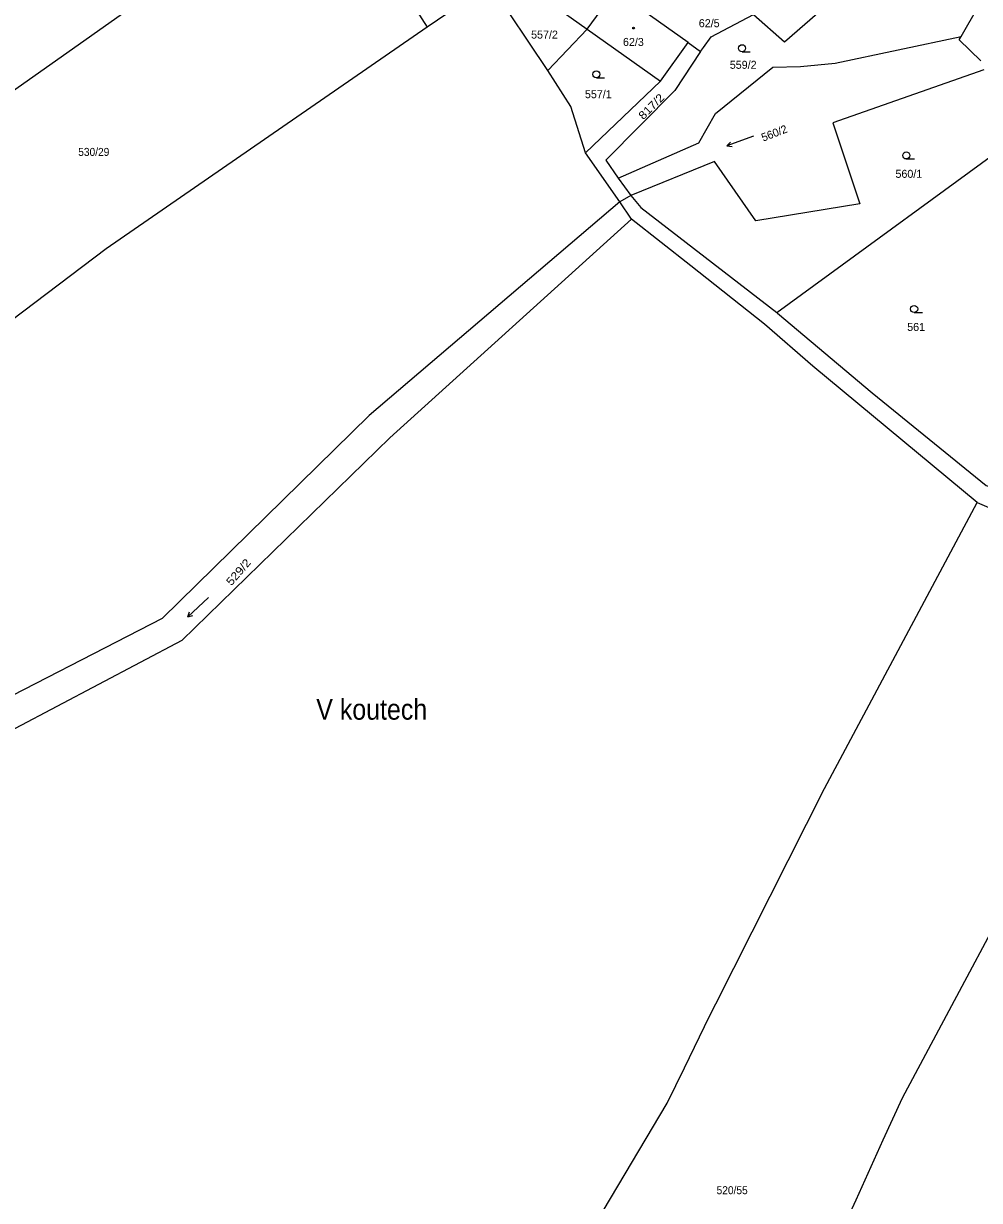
# Model space of a CAD drawing. Extents: x -687135 to -684370, y -1007309 to -1005782.
# Drawn here: x -685399.4 to -685196.4, y -1006924.3 to -1006674.4 of the extents above; entities that cross this region are included whole.
import ezdxf
from ezdxf.enums import TextEntityAlignment as Align

# ---------------------------------------------------------------- set-up
doc = ezdxf.new("R2010")
doc.units = 0
doc.header["$LTSCALE"] = 0.68
for name, color, linetype, lineweight in [('1', 7, 'Continuous', 25), ('3', 7, 'Continuous', 25), ('5', 7, 'Continuous', 25), ('7', 7, 'Continuous', 13)]:
    doc.layers.add(name, color=color, linetype=linetype, lineweight=lineweight)
doc.layers.add('2', color=7, linetype='Continuous')

msp = doc.modelspace()

# ---------------------------------------------------------------- linework, layer by layer
at = {"layer": '1'}
for p, q in [((-685335.02, -1006641.79), (-685313.7, -1006675.14)), ((-685279.72, -1006675.62), (-685273.74, -1006667.38)), ((-685279.72, -1006675.62), (-685288.04, -1006684.34)), ((-685258.28, -1006678.42), (-685255.62, -1006680.32)), ((-685280.06, -1006701.85), (-685264.15, -1006686.64)), ((-685272.78, -1006712.27), (-685280.06, -1006701.85)), ((-685273.1, -1006707.25), (-685270.46, -1006710.92)), ((-685270.46, -1006710.92), (-685272.78, -1006712.27)), ((-685270.27, -1006715.95), (-685272.78, -1006712.27)), ((-685196.87, -1006776.1), (-685155.44, -1006794.14))]:
    msp.add_line(p, q, dxfattribs=at)
for points in [[(-685413.15, -1006696.73), (-685384.89, -1006676.88), (-685341.29, -1006645.97), (-685335.02, -1006641.79)], [(-685273.1, -1006707.25), (-685256.03, -1006699.69), (-685252.45, -1006693.52), (-685240.26, -1006683.63), (-685234.38, -1006683.48), (-685227.07, -1006682.77), (-685200.27, -1006677.13), (-685196.71, -1006670.85), (-685212.49, -1006656.18)], [(-685244.38, -1006672.48), (-685237.81, -1006678.26), (-685212.49, -1006656.18)], [(-685296.58, -1006663.55), (-685287.7, -1006669.89), (-685279.72, -1006675.62)], [(-685280.06, -1006701.85), (-685283.18, -1006692.03), (-685288.04, -1006684.34), (-685300.34, -1006666.05), (-685313.7, -1006675.14)], [(-685279.72, -1006675.62), (-685264.15, -1006686.64), (-685258.28, -1006678.42), (-685273.74, -1006667.38)], [(-685255.62, -1006680.32), (-685255.04, -1006679.45), (-685253.41, -1006677.18), (-685244.38, -1006672.48)], [(-685313.7, -1006675.14), (-685381.87, -1006722.26), (-685417.2, -1006748.9), (-685442.1, -1006766.87), (-685471.35, -1006787.14), (-685521.55, -1006819.13)], [(-685196.12, -1006682.34), (-685200.74, -1006677.86), (-685200.27, -1006677.13)], [(-685255.62, -1006680.32), (-685261.11, -1006688.62), (-685275.78, -1006703.42), (-685273.1, -1006707.25)], [(-685195.49, -1006684.24), (-685227.55, -1006695.45), (-685221.81, -1006712.7), (-685243.9, -1006716.28), (-685252.71, -1006703.66), (-685270.46, -1006710.92)], [(-685270.46, -1006710.92), (-685268.32, -1006713.45), (-685239.42, -1006735.75), (-685184.75, -1006695.82)], [(-685272.78, -1006712.27), (-685326.02, -1006757.61), (-685369.95, -1006800.7), (-685411.54, -1006822.08), (-685479.62, -1006851.9)], [(-685270.27, -1006715.95), (-685321.6, -1006762.38), (-685365.8, -1006805.42), (-685410.08, -1006828.78), (-685472.04, -1006855.16)], [(-685196.87, -1006776.1), (-685231.83, -1006747.11), (-685242.03, -1006738.2), (-685257.69, -1006725.86), (-685270.27, -1006715.95)], [(-685239.42, -1006735.75), (-685239.28, -1006735.88), (-685219.19, -1006752.8), (-685194.99, -1006772.45), (-685194.34, -1006772.72)], [(-685344.34, -1007065.04), (-685332.49, -1007031.1), (-685312.53, -1006989.57), (-685304.62, -1006974.15), (-685262.73, -1006903.67), (-685259.07, -1006896.13), (-685253.74, -1006885.14), (-685252.41, -1006882.51), (-685229.3, -1006836.82), (-685196.87, -1006776.1)], [(-685301.77, -1007070.79), (-685288.08, -1007040.77), (-685248.53, -1006968.29), (-685233.07, -1006943.13), (-685224.8, -1006928.93), (-685222.62, -1006924.15), (-685216.83, -1006911.45), (-685212.76, -1006902.52), (-685180.81, -1006842.75), (-685155.44, -1006794.14)]]:
    msp.add_lwpolyline(points, dxfattribs=at)
at = {"layer": '3'}
for p, q in [((-685246.823, -1006680.38), (-685245.073, -1006680.38)), ((-685277.763, -1006685.92), (-685276.013, -1006685.92)), ((-685250.048, -1006700.374), (-685249.301, -1006699.568)), ((-685211.953, -1006703.15), (-685210.203, -1006703.15)), ((-685210.283, -1006735.75), (-685208.533, -1006735.75)), ((-685364.512, -1006800.361), (-685364.14, -1006799.328))]:
    msp.add_line(p, q, dxfattribs=at)
for points in [[(-685244.41, -1006698.322), (-685250.048, -1006700.374), (-685248.958, -1006700.511)], [(-685360.124, -1006796.269), (-685364.512, -1006800.361), (-685363.456, -1006800.062)]]:
    msp.add_lwpolyline(points, dxfattribs=at)
for centre in [(-685246.8229, -1006679.6298), (-685277.7629, -1006685.1698), (-685211.9529, -1006702.3998), (-685210.2829, -1006734.9998)]:
    msp.add_circle(centre, 0.75, dxfattribs=at)
at = {"layer": '5'}
msp.add_circle((-685269.8668, -1006675.3592), 0.175, dxfattribs=at)

# ---------------------------------------------------------------- texts
at = {"layer": '2'}
for s, p in [('62/5', (-685256.01, -1006675.169)), ('557/2', (-685291.62, -1006677.59)), ('62/3', (-685272.11, -1006679.15)), ('559/2', (-685249.43, -1006684)), ('557/1', (-685280.19, -1006690.24)), ('560/1', (-685214.25, -1006707.15)), ('561', (-685211.76, -1006739.669))]:
    msp.add_text(s, height=1.7, dxfattribs=at).set_placement(p)
at = {"layer": '2', "width": 1.15}
for s, rotation, p in [('817/2', 45, (-685267.808, -1006694.921)), ('529/2', 49, (-685355.268, -1006793.887))]:
    msp.add_text(s, height=1.7, rotation=rotation, dxfattribs=at).set_placement(p)
at = {"layer": '2'}
msp.add_text('560/2', height=1.7, rotation=21, dxfattribs=at).set_placement((-685242.335, -1006699.473))
at = {"layer": '2', "width": 0.95}
for s, p in [('530/29', (-685387.78, -1006702.5)), ('520/55', (-685252.23, -1006922.97))]:
    msp.add_text(s, height=1.7, dxfattribs=at).set_placement(p)
at = {"layer": '7', "width": 0.9}
msp.add_text('V koutech', height=4.4, dxfattribs=at).set_placement((-685325.459, -1006822.21), align=Align.CENTER)

doc.saveas('drawing.dxf')
